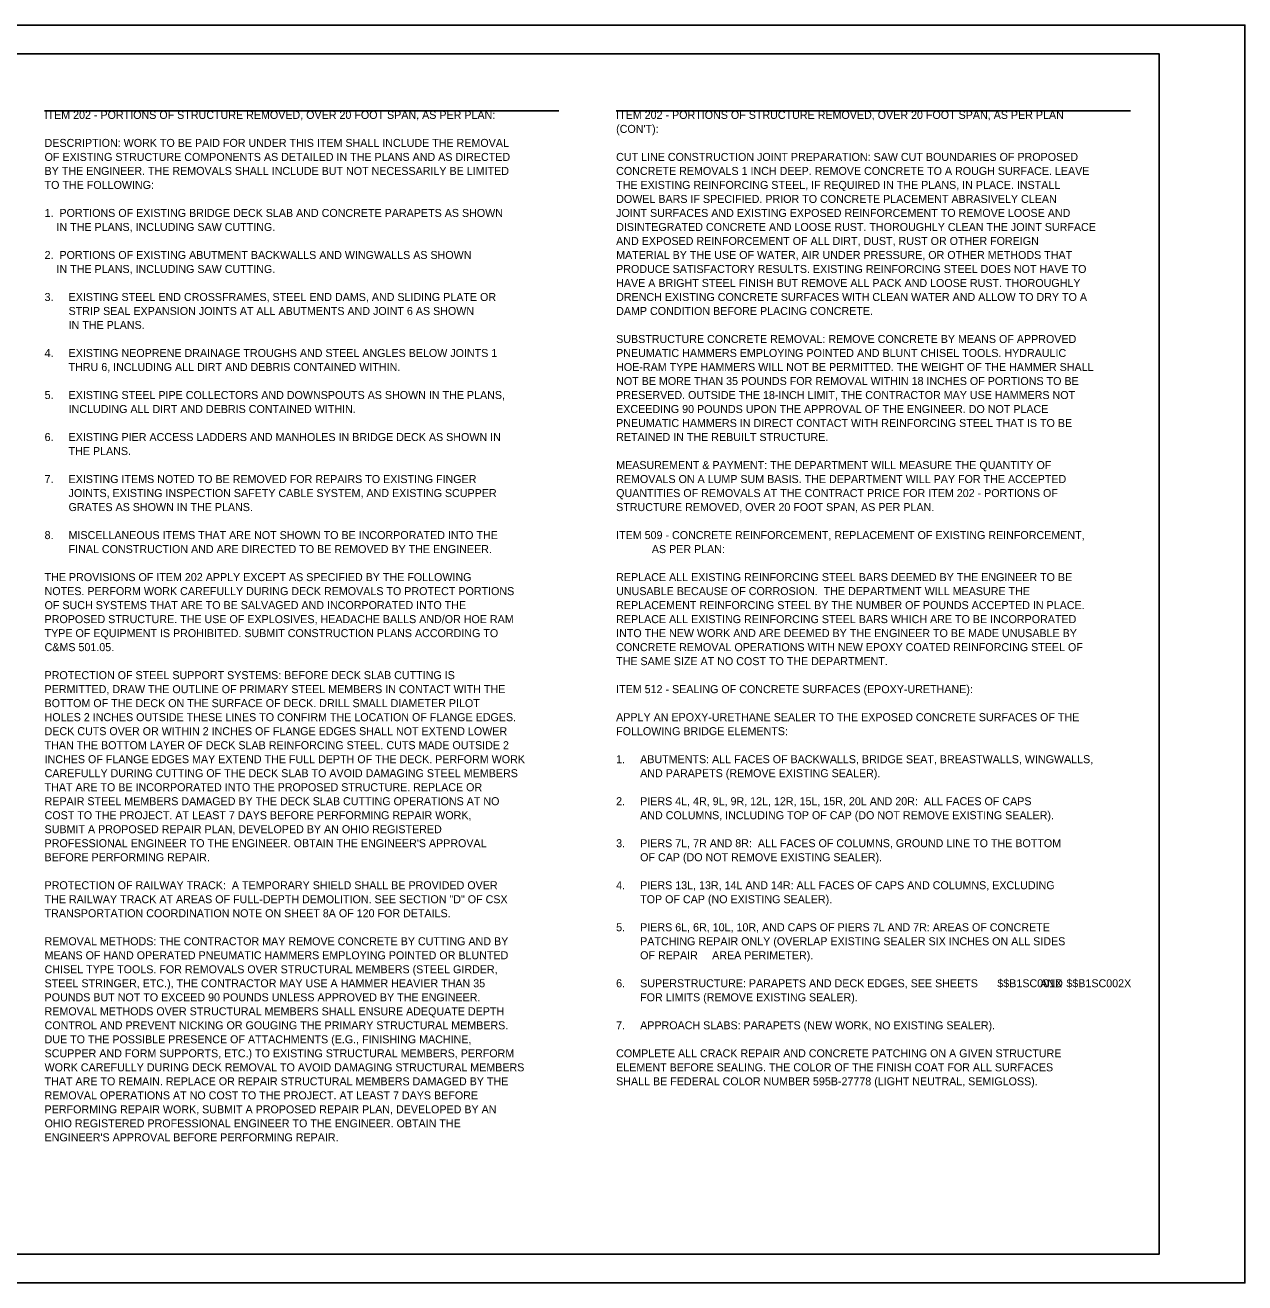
# Model space of a CAD drawing. Extents: x 0 to 72, y -26 to 50.
# Drawn here: x 12.66 to 34, y 26 to 48 of the extents above; entities that cross this region are included whole.
import ezdxf

# ---------------------------------------------------------------- set-up
doc = ezdxf.new("R2010")
doc.units = 0
doc.layers.add('SH_Cut_Line', color=7, linetype='Continuous')
doc.layers.add('SH_Data', color=7, linetype='Continuous')

msp = doc.modelspace()

# ---------------------------------------------------------------- linework, layer by layer
at = {"layer": 'SH_Cut_Line'}
for p, q in [((13, 46.5), (22, 46.5)), ((23, 46.5), (32, 46.5)), ((23, 46.5), (32, 46.5))]:
    msp.add_line(p, q, dxfattribs=at)
for points in [[(0, 48), (34, 48), (34, 26), (0, 26)], [(2, 47.5), (32.5, 47.5), (32.5, 26.5), (2, 26.5)]]:
    msp.add_lwpolyline(points, close=True, dxfattribs=at)

# ---------------------------------------------------------------- texts
at = {"layer": 'SH_Data'}
for s, p in [('ITEM 202 - PORTIONS OF STRUCTURE REMOVED, OVER 20 FOOT SPAN, AS PER PLAN:', (13, 46.36)), ('ITEM 202 - PORTIONS OF STRUCTURE REMOVED, OVER 20 FOOT SPAN, AS PER PLAN:', (13, 46.36)), ('ITEM 202 - PORTIONS OF STRUCTURE REMOVED, OVER 20 FOOT SPAN, AS PER PLAN ', (23, 46.36)), ('ITEM 202 - PORTIONS OF STRUCTURE REMOVED, OVER 20 FOOT SPAN, AS PER PLAN ', (23, 46.36)), ("(CON'T):", (23, 46.115)), ("(CON'T):", (23, 46.115)), ('DESCRIPTION: WORK TO BE PAID FOR UNDER THIS ITEM SHALL INCLUDE THE REMOVAL ', (13, 45.87)), ('OF EXISTING STRUCTURE COMPONENTS AS DETAILED IN THE PLANS AND AS DIRECTED ', (13, 45.625)), ('CUT LINE CONSTRUCTION JOINT PREPARATION: SAW CUT BOUNDARIES OF PROPOSED ', (23, 45.625)), ('BY THE ENGINEER. THE REMOVALS SHALL INCLUDE BUT NOT NECESSARILY BE LIMITED ', (13, 45.38)), ('CONCRETE REMOVALS 1 INCH DEEP. REMOVE CONCRETE TO A ROUGH SURFACE. LEAVE ', (23, 45.38)), ('TO THE FOLLOWING:', (13, 45.135)), ('THE EXISTING REINFORCING STEEL, IF REQUIRED IN THE PLANS, IN PLACE. INSTALL ', (23, 45.135)), ('DOWEL BARS IF SPECIFIED. PRIOR TO CONCRETE PLACEMENT ABRASIVELY CLEAN ', (23, 44.89)), ('1.  PORTIONS OF EXISTING BRIDGE DECK SLAB AND CONCRETE PARAPETS AS SHOWN', (13, 44.645)), ('JOINT SURFACES AND EXISTING EXPOSED REINFORCEMENT TO REMOVE LOOSE AND ', (23, 44.645)), ('    IN THE PLANS, INCLUDING SAW CUTTING.', (13, 44.4)), ('DISINTEGRATED CONCRETE AND LOOSE RUST. THOROUGHLY CLEAN THE JOINT SURFACE ', (23, 44.4)), ('AND EXPOSED REINFORCEMENT OF ALL DIRT, DUST, RUST OR OTHER FOREIGN ', (23, 44.155)), ('2.  PORTIONS OF EXISTING ABUTMENT BACKWALLS AND WINGWALLS AS SHOWN', (13, 43.91)), ('MATERIAL BY THE USE OF WATER, AIR UNDER PRESSURE, OR OTHER METHODS THAT ', (23, 43.91)), ('    IN THE PLANS, INCLUDING SAW CUTTING.', (13, 43.665)), ('PRODUCE SATISFACTORY RESULTS. EXISTING REINFORCING STEEL DOES NOT HAVE TO ', (23, 43.665)), ('HAVE A BRIGHT STEEL FINISH BUT REMOVE ALL PACK AND LOOSE RUST. THOROUGHLY ', (23, 43.42)), ('3.', (13, 43.175)), ('EXISTING STEEL END CROSSFRAMES, STEEL END DAMS, AND SLIDING PLATE OR', (13.42, 43.175)), ('DRENCH EXISTING CONCRETE SURFACES WITH CLEAN WATER AND ALLOW TO DRY TO A ', (23, 43.175)), ('STRIP SEAL EXPANSION JOINTS AT ALL ABUTMENTS AND JOINT 6 AS SHOWN', (13.42, 42.93)), ('DAMP CONDITION BEFORE PLACING CONCRETE. ', (23, 42.93)), ('IN THE PLANS.', (13.42, 42.685)), ('SUBSTRUCTURE CONCRETE REMOVAL: REMOVE CONCRETE BY MEANS OF APPROVED ', (23, 42.44)), ('4.', (13, 42.195)), ('EXISTING NEOPRENE DRAINAGE TROUGHS AND STEEL ANGLES BELOW JOINTS 1 ', (13.42, 42.195)), ('PNEUMATIC HAMMERS EMPLOYING POINTED AND BLUNT CHISEL TOOLS. HYDRAULIC ', (23, 42.195)), ('THRU 6, INCLUDING ALL DIRT AND DEBRIS CONTAINED WITHIN.', (13.42, 41.95)), ('HOE-RAM TYPE HAMMERS WILL NOT BE PERMITTED. THE WEIGHT OF THE HAMMER SHALL ', (23, 41.95)), ('NOT BE MORE THAN 35 POUNDS FOR REMOVAL WITHIN 18 INCHES OF PORTIONS TO BE ', (23, 41.705)), ('5.', (13, 41.46)), ('EXISTING STEEL PIPE COLLECTORS AND DOWNSPOUTS AS SHOWN IN THE PLANS,', (13.42, 41.46)), ('PRESERVED. OUTSIDE THE 18-INCH LIMIT, THE CONTRACTOR MAY USE HAMMERS NOT ', (23, 41.46)), ('INCLUDING ALL DIRT AND DEBRIS CONTAINED WITHIN.', (13.42, 41.215)), ('EXCEEDING 90 POUNDS UPON THE APPROVAL OF THE ENGINEER. DO NOT PLACE ', (23, 41.215)), ('PNEUMATIC HAMMERS IN DIRECT CONTACT WITH REINFORCING STEEL THAT IS TO BE ', (23, 40.97)), ('6.', (13, 40.725)), ('EXISTING PIER ACCESS LADDERS AND MANHOLES IN BRIDGE DECK AS SHOWN IN', (13.42, 40.725)), ('RETAINED IN THE REBUILT STRUCTURE.', (23, 40.725)), ('THE PLANS.', (13.42, 40.48)), ('MEASUREMENT & PAYMENT: THE DEPARTMENT WILL MEASURE THE QUANTITY OF ', (23, 40.235)), ('7.', (13, 39.99)), ('EXISTING ITEMS NOTED TO BE REMOVED FOR REPAIRS TO EXISTING FINGER', (13.42, 39.99)), ('REMOVALS ON A LUMP SUM BASIS. THE DEPARTMENT WILL PAY FOR THE ACCEPTED ', (23, 39.99)), ('JOINTS, EXISTING INSPECTION SAFETY CABLE SYSTEM, AND EXISTING SCUPPER', (13.42, 39.745)), ('QUANTITIES OF REMOVALS AT THE CONTRACT PRICE FOR ITEM 202 - PORTIONS OF ', (23, 39.745)), ('GRATES AS SHOWN IN THE PLANS.', (13.42, 39.5)), ('STRUCTURE REMOVED, OVER 20 FOOT SPAN, AS PER PLAN.', (23, 39.5)), ('8.', (13, 39.01)), ('MISCELLANEOUS ITEMS THAT ARE NOT SHOWN TO BE INCORPORATED INTO THE', (13.42, 39.01)), ('ITEM 509 - CONCRETE REINFORCEMENT, REPLACEMENT OF EXISTING REINFORCEMENT,', (23, 39.01)), ('ITEM 509 - CONCRETE REINFORCEMENT, REPLACEMENT OF EXISTING REINFORCEMENT,', (23, 39.01)), ('FINAL CONSTRUCTION AND ARE DIRECTED TO BE REMOVED BY THE ENGINEER.', (13.42, 38.765)), ('            AS PER PLAN:', (23, 38.765)), ('            AS PER PLAN:', (23, 38.765)), ('THE PROVISIONS OF ITEM 202 APPLY EXCEPT AS SPECIFIED BY THE FOLLOWING ', (13, 38.275)), ('REPLACE ALL EXISTING REINFORCING STEEL BARS DEEMED BY THE ENGINEER TO BE ', (23, 38.275)), ('NOTES. PERFORM WORK CAREFULLY DURING DECK REMOVALS TO PROTECT PORTIONS ', (13, 38.03)), ('UNUSABLE BECAUSE OF CORROSION.  THE DEPARTMENT WILL MEASURE THE ', (23, 38.03)), ('OF SUCH SYSTEMS THAT ARE TO BE SALVAGED AND INCORPORATED INTO THE ', (13, 37.785)), ('REPLACEMENT REINFORCING STEEL BY THE NUMBER OF POUNDS ACCEPTED IN PLACE.  ', (23, 37.785)), ('PROPOSED STRUCTURE. THE USE OF EXPLOSIVES, HEADACHE BALLS AND/OR HOE RAM ', (13, 37.54)), ('REPLACE ALL EXISTING REINFORCING STEEL BARS WHICH ARE TO BE INCORPORATED ', (23, 37.54)), ('TYPE OF EQUIPMENT IS PROHIBITED. SUBMIT CONSTRUCTION PLANS ACCORDING TO ', (13, 37.295)), ('INTO THE NEW WORK AND ARE DEEMED BY THE ENGINEER TO BE MADE UNUSABLE BY ', (23, 37.295)), ('C&MS 501.05.', (13, 37.05)), ('CONCRETE REMOVAL OPERATIONS WITH NEW EPOXY COATED REINFORCING STEEL OF ', (23, 37.05)), ('THE SAME SIZE AT NO COST TO THE DEPARTMENT.', (23, 36.805)), ('PROTECTION OF STEEL SUPPORT SYSTEMS: BEFORE DECK SLAB CUTTING IS ', (13, 36.56)), ('PERMITTED, DRAW THE OUTLINE OF PRIMARY STEEL MEMBERS IN CONTACT WITH THE ', (13, 36.315)), ('ITEM 512 - SEALING OF CONCRETE SURFACES (EPOXY-URETHANE):', (23, 36.315)), ('ITEM 512 - SEALING OF CONCRETE SURFACES (EPOXY-URETHANE):', (23, 36.315)), ('BOTTOM OF THE DECK ON THE SURFACE OF DECK. DRILL SMALL DIAMETER PILOT ', (13, 36.07)), ('HOLES 2 INCHES OUTSIDE THESE LINES TO CONFIRM THE LOCATION OF FLANGE EDGES. ', (13, 35.825)), ('APPLY AN EPOXY-URETHANE SEALER TO THE EXPOSED CONCRETE SURFACES OF THE ', (23, 35.825)), ('DECK CUTS OVER OR WITHIN 2 INCHES OF FLANGE EDGES SHALL NOT EXTEND LOWER ', (13, 35.58)), ('FOLLOWING BRIDGE ELEMENTS:', (23, 35.58)), ('THAN THE BOTTOM LAYER OF DECK SLAB REINFORCING STEEL. CUTS MADE OUTSIDE 2 ', (13, 35.335)), ('INCHES OF FLANGE EDGES MAY EXTEND THE FULL DEPTH OF THE DECK. PERFORM WORK ', (13, 35.09)), ('1.', (23, 35.09)), ('ABUTMENTS: ALL FACES OF BACKWALLS, BRIDGE SEAT, BREASTWALLS, WINGWALLS, ', (23.42, 35.09)), ('CAREFULLY DURING CUTTING OF THE DECK SLAB TO AVOID DAMAGING STEEL MEMBERS ', (13, 34.845)), ('AND PARAPETS (REMOVE EXISTING SEALER).', (23.42, 34.845)), ('THAT ARE TO BE INCORPORATED INTO THE PROPOSED STRUCTURE. REPLACE OR ', (13, 34.6)), ('REPAIR STEEL MEMBERS DAMAGED BY THE DECK SLAB CUTTING OPERATIONS AT NO ', (13, 34.355)), ('2.', (23, 34.355)), ('PIERS 4L, 4R, 9L, 9R, 12L, 12R, 15L, 15R, 20L AND 20R:  ALL FACES OF CAPS', (23.42, 34.355)), ('COST TO THE PROJECT. AT LEAST 7 DAYS BEFORE PERFORMING REPAIR WORK, ', (13, 34.11)), ('AND COLUMNS, INCLUDING TOP OF CAP (DO NOT REMOVE EXISTING SEALER).', (23.42, 34.11)), ('SUBMIT A PROPOSED REPAIR PLAN, DEVELOPED BY AN OHIO REGISTERED ', (13, 33.865)), ("PROFESSIONAL ENGINEER TO THE ENGINEER. OBTAIN THE ENGINEER'S APPROVAL ", (13, 33.62)), ('3.', (23, 33.62)), ('PIERS 7L, 7R AND 8R:  ALL FACES OF COLUMNS, GROUND LINE TO THE BOTTOM', (23.42, 33.62)), ('BEFORE PERFORMING REPAIR.', (13, 33.375)), ('OF CAP (DO NOT REMOVE EXISTING SEALER).', (23.42, 33.375)), ('PROTECTION OF RAILWAY TRACK:  A TEMPORARY SHIELD SHALL BE PROVIDED OVER ', (13, 32.885)), ('4.', (23, 32.885)), ('PIERS 13L, 13R, 14L AND 14R: ALL FACES OF CAPS AND COLUMNS, EXCLUDING', (23.42, 32.885)), ('THE RAILWAY TRACK AT AREAS OF FULL-DEPTH DEMOLITION. SEE SECTION "D" OF CSX ', (13, 32.64)), ('TOP OF CAP (NO EXISTING SEALER).', (23.42, 32.64)), ('TRANSPORTATION COORDINATION NOTE ON SHEET 8A OF 120 FOR DETAILS.', (13, 32.395)), ('5.', (23, 32.15)), ('PIERS 6L, 6R, 10L, 10R, AND CAPS OF PIERS 7L AND 7R: AREAS OF CONCRETE', (23.42, 32.15)), ('REMOVAL METHODS: THE CONTRACTOR MAY REMOVE CONCRETE BY CUTTING AND BY ', (13, 31.905)), ('PATCHING REPAIR ONLY (OVERLAP EXISTING SEALER SIX INCHES ON ALL SIDES', (23.42, 31.905)), ('MEANS OF HAND OPERATED PNEUMATIC HAMMERS EMPLOYING POINTED OR BLUNTED ', (13, 31.66)), ('OF REPAIR', (23.42, 31.66)), ('AREA PERIMETER).', (24.68, 31.66)), ('CHISEL TYPE TOOLS. FOR REMOVALS OVER STRUCTURAL MEMBERS (STEEL GIRDER, ', (13, 31.415)), ('STEEL STRINGER, ETC.), THE CONTRACTOR MAY USE A HAMMER HEAVIER THAN 35 ', (13, 31.17)), ('6.', (23, 31.17)), ('SUPERSTRUCTURE: PARAPETS AND DECK EDGES, SEE SHEETS ', (23.42, 31.17)), ('$$B1SC001X', (29.67, 31.17)), ('AND', (30.42, 31.17)), ('$$B1SC002X', (30.878, 31.17)), ('POUNDS BUT NOT TO EXCEED 90 POUNDS UNLESS APPROVED BY THE ENGINEER. ', (13, 30.925)), ('FOR LIMITS (REMOVE EXISTING SEALER).', (23.42, 30.925)), ('REMOVAL METHODS OVER STRUCTURAL MEMBERS SHALL ENSURE ADEQUATE DEPTH ', (13, 30.68)), ('APPROACH SLABS: PARAPETS (NEW WORK, NO EXISTING SEALER).', (23.42, 30.435)), ('CONTROL AND PREVENT NICKING OR GOUGING THE PRIMARY STRUCTURAL MEMBERS. ', (13, 30.435)), ('7.', (23, 30.435)), ('DUE TO THE POSSIBLE PRESENCE OF ATTACHMENTS (E.G., FINISHING MACHINE, ', (13, 30.19)), ('SCUPPER AND FORM SUPPORTS, ETC.) TO EXISTING STRUCTURAL MEMBERS, PERFORM ', (13, 29.945)), ('COMPLETE ALL CRACK REPAIR AND CONCRETE PATCHING ON A GIVEN STRUCTURE ', (23, 29.945)), ('WORK CAREFULLY DURING DECK REMOVAL TO AVOID DAMAGING STRUCTURAL MEMBERS ', (13, 29.7)), ('ELEMENT BEFORE SEALING. THE COLOR OF THE FINISH COAT FOR ALL SURFACES ', (23, 29.7)), ('THAT ARE TO REMAIN. REPLACE OR REPAIR STRUCTURAL MEMBERS DAMAGED BY THE ', (13, 29.455)), ('SHALL BE FEDERAL COLOR NUMBER 595B-27778 (LIGHT NEUTRAL, SEMIGLOSS). ', (23, 29.455)), ('REMOVAL OPERATIONS AT NO COST TO THE PROJECT. AT LEAST 7 DAYS BEFORE ', (13, 29.21)), ('PERFORMING REPAIR WORK, SUBMIT A PROPOSED REPAIR PLAN, DEVELOPED BY AN ', (13, 28.965)), ('OHIO REGISTERED PROFESSIONAL ENGINEER TO THE ENGINEER. OBTAIN THE ', (13, 28.72)), ("ENGINEER'S APPROVAL BEFORE PERFORMING REPAIR.", (13, 28.475))]:
    msp.add_text(s, height=0.14, dxfattribs=at).set_placement(p)

doc.saveas('drawing.dxf')
